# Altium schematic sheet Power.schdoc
size 297 x 209 mm; Symbol: Drawing-Symbol_A4; @Project Name: Pedal Steel; @Page Count: 1; @Update Date: 2026-10-20; @Create Date: 2026-10-20; @Schematic Name: Schematic1; @Page No: 1; @Page Name: P1; Company: EasyEDA.com; Version: V1.0; Page Size: A4; Device: Drawing-Symbol_A4; @Create Time: 16:14:21; @Update Time: 16:14:21; Border: 1; Width: 1170; Height: 825; Region Start: 1; X Region Count: 6; Y Region Count: 4; Blade Width: 10; Title Block Position: 3; @Board Name: Board1
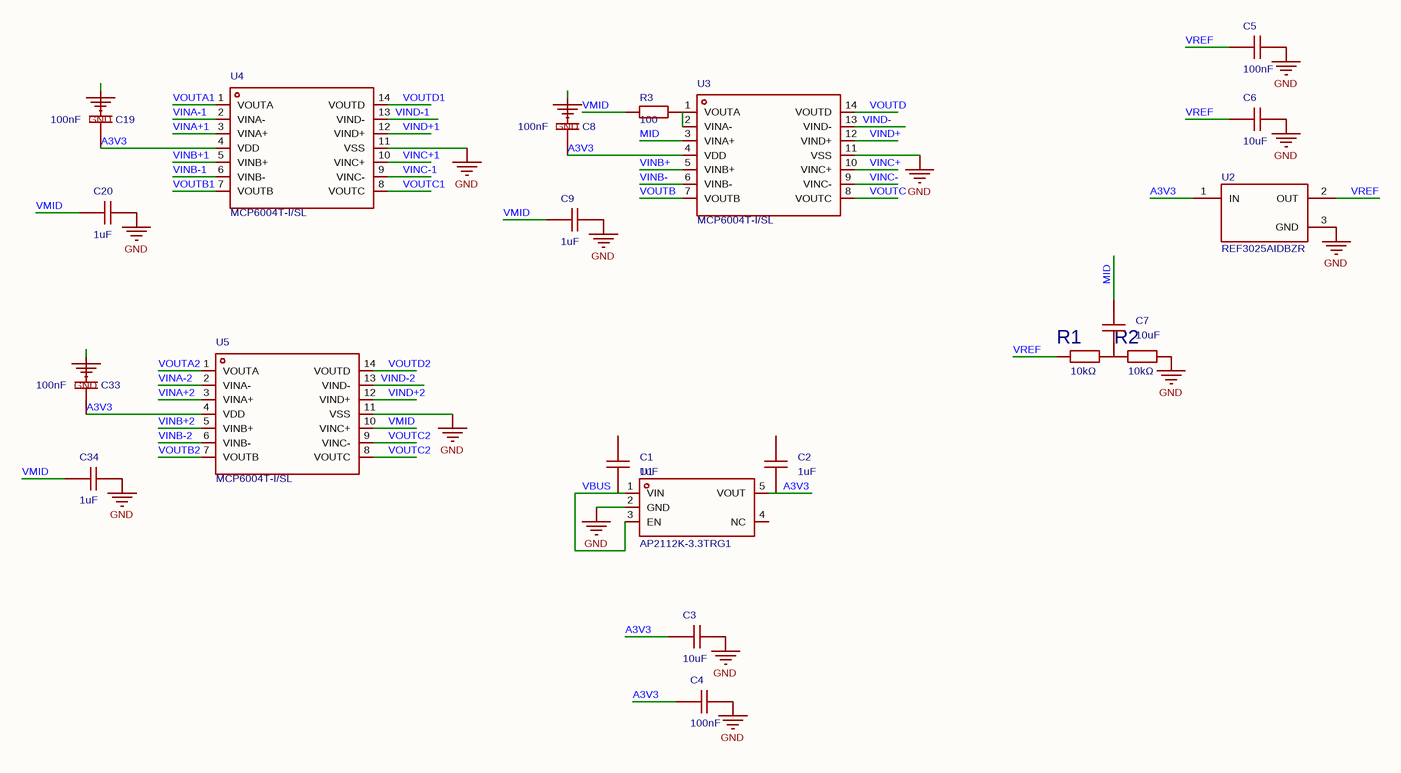
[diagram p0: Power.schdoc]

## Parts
C1  1uF  [C0603]
C2  1uF  [C0603]
C3  10uF  [C0603]
C4  100nF  [C0603]
C5  100nF  [C0603]
C6  10uF  [C0603]
C7  10uF  [C0603]
C8  100nF  [C0603]
C9  1uF  [C0603]
C19  100nF  [C0603]
C20  1uF  [C0603]
C33  100nF  [C0603]
C34  1uF  [C0603]
R1  10kΩ  [R0603]
R2  10kΩ  [R0603]
R3  100  [R0603]
U1  AP2112K-3.3TRG1  [SOT-25-5_L2.9-W1.6-P0.95-LS2.8-BL]
U2  REF3025AIDBZR  [SOT-23-3_L2.9-W1.6-P1.90-LS2.8-BR]
U3  MCP6004T-I/SL  [SOIC-14_L8.7-W3.9-P1.27-LS6.0-BL]
U4  MCP6004T-I/SL  [SOIC-14_L8.7-W3.9-P1.27-LS6.0-BL]
U5  MCP6004T-I/SL  [SOIC-14_L8.7-W3.9-P1.27-LS6.0-BL]

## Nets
GND: C3.1 C4.1 C5.1 C6.1 C8.1 C9.1 C19.1 C20.1 C33.1 C34.1 R2.2 U1.2(GND) U2.3(GND) U3.11(VSS) U4.11(VSS) U5.11(VSS)
A3V3: C2.2 C3.2 C4.2 C8.2 C19.2 C33.2 U1.5(VOUT) U2.1(IN) U3.4(VDD) U4.4(VDD) U5.4(VDD)
MID: C7.1 U3.3(VINA+)
VBUS: C1.2 U1.1(VIN) U1.3(EN)
VINA+1: U4.3(VINA+)
VINA+2: U5.3(VINA+)
VINA-1: U4.2(VINA-)
VINA-2: U5.2(VINA-)
VINB+: U3.5(VINB+)
VINB+1: U4.5(VINB+)
VINB+2: U5.5(VINB+)
VINB-: U3.6(VINB-)
VINB-1: U4.6(VINB-)
VINB-2: U5.6(VINB-)
VINC+: U3.10(VINC+)
VINC+1: U4.10(VINC+)
VINC-: U3.9(VINC-)
VINC-1: U4.9(VINC-)
VIND+: U3.12(VIND+)
VIND+1: U4.12(VIND+)
VIND+2: U5.12(VIND+)
VIND-: U3.13(VIND-)
VIND-1: U4.13(VIND-)
VIND-2: U5.13(VIND-)
VMID: C9.2 C20.2 C34.2 R3.1 U5.10(VINC+)
VOUTA1: U4.1(VOUTA)
VOUTA2: U5.1(VOUTA)
VOUTB: U3.7(VOUTB)
VOUTB1: U4.7(VOUTB)
VOUTB2: U5.7(VOUTB)
VOUTC: U3.8(VOUTC)
VOUTC1: U4.8(VOUTC)
VOUTC2: U5.8(VOUTC) U5.9(VINC-)
VOUTD: U3.14(VOUTD)
VOUTD1: U4.14(VOUTD)
VOUTD2: U5.14(VOUTD)
VREF: C5.2 C6.2 R1.1 U2.2(OUT)
NetC7_2: C7.2 R1.2 R2.1
NetR3_2: R3.2 U3.1(VOUTA) U3.2(VINA-)

Not connected (* = marked no-connect by the designer): C1 1; C2 1; U1 4(NC)

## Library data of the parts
C1-C9 C19 C20 C33 C34 = CAP_0603: Symbol: CAP_OLD; ConvertToPcb: yes; ModelId: 624118aa3cc7497086c383c2d72e08520819f05c4eef4c71ace90d822a990e87; ModelName: C0603_L1.6-W0.8-H0.8; ModelTransform: 62.992,31.496,0,0,0,0,0,0,0
R1 R2 = 0603WAF1002T5E: Type:Thick Film Resistor Resistance:10kΩ Tolerance:±1% Tolerance:±1% Power(Watts):100mW Voltage-Supply(Max):75V Temperature Coefficient:±100ppm/℃ Temperature Coefficient:±100ppm/℃ Operating Temperature:-55℃~+155℃ Operating Temperature:-55℃~+155℃; Manufacturer: UNI-ROYAL(厚声); AddInBom: yes; ModelId: 112863783b5b41f1b5254f87eedc79320819f05c4eef4c71ace90d822a990e87; ModelTransform: 31.8897,63.7794,0,90,0,0,0,0,0; Tolerance: ±1%; Power(Watts): 100mW; Voltage-Supply(Max): 75V
R3 = Res_0603: Symbol: Res; ConvertToPcb: yes; ModelId: 112863783b5b41f1b5254f87eedc79320819f05c4eef4c71ace90d822a990e87; ModelTransform: 31.8897,63.7794,0,90,0,0,0,0,0
U1 = AP2112K-3.3TRG1: Output Configuration:Positive Voltage - Supply:6V Output Voltage:3.3V Output Voltage:3.3V Output Current:600mA Power Supply Rejection Ratio (PSRR):65dB@(1kHz) Voltage Dropout:250mV@(600mA) standby current:55uA Noise:50uVrms Features:Enable control；Short C; Manufacturer: DIODES(美台); AddInBom: yes; ModelId: 6177bbcd6fc94df4b4ba2f22405723a00819f05c4eef4c71ace90d822a990e87; ModelTransform: 114.173,110.236,0,0,0,0,0,0,0; Voltage - Supply: 6V; Output Voltage: 3.3V; standby current: 55uA; Output Type: Fixed; Number of Outputs: 1
U2 = REF3025AIDBZR: Output Type:Fixed Voltage - Supply:2.55V~5.5V Voltage - Supply:2.55V~5.5V Output Voltage:2.5V Output Voltage:2.5V Output Current:25mA Tolerance:±0.2% Tolerance:±0.2% Temperature Coefficient:75ppm/℃ Reference Type:Series Quiescent Current:50uA Minimum Cath; Manufacturer: TI(德州仪器); AddInBom: yes; ModelId: 4eed685bb9f4439b846746bc2193f3c00819f05c4eef4c71ace90d822a990e87; ModelName: SOT-23-3L_L2.9-W1.6-H1.1-LS2.8-P0.95; ModelTransform: 114.173,110.236,0,90,0,0,0,0,0; Output Type: Fixed; Output Voltage: 2.5V; Output Current: 25mA; Tolerance: ±0.2%; Reference Type: Series; Quiescent Current: 50uA; Noise - 1/10Hz to 10Hz: 28uVp-p; Noise - 10Hz to 10kHz: 80uVrms
U3-U5 = MCP6004T-I/SL: Number of Channels:4 Rail to Rail:Rail-to-Rail Input, Rail-to-Rail Output Gain Bandwidth Product:1MHz Vos - Input Offset Voltage:4.5mV Input Offset Voltage Drift(Vos TC):2uV/℃ Slew Rate:600V/ms Ib - Input Bias Current:1pA Input Offset Current(Ios):1pA Inp; Manufacturer: MICROCHIP(美国微芯); AddInBom: yes; ModelId: 4a4abff9a5634443a503282266e866970819f05c4eef4c71ace90d822a990e87; ModelName: SOIC-14_L8.6-W3.9-H1.8-LS6.0-P1.27; ModelTransform: 338.583,236.22,0,0,0,0,0,0.001,0; Number of Channels: 4; Gain Bandwidth Product: 1MHz; Vos - Input Offset Voltage: 4.5mV; Input Offset Voltage Drift(Vos TC): 2uV/℃; Ib - Input Bias Current: 1pA; Input Voltage Noise Density: 28nV/√Hz@1kHz; Common Mode Rejection Ratio(CMRR): 76dB; Quiescent Current: 100uA; Output Current: 23mA; Single supply: 1.8V~6V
